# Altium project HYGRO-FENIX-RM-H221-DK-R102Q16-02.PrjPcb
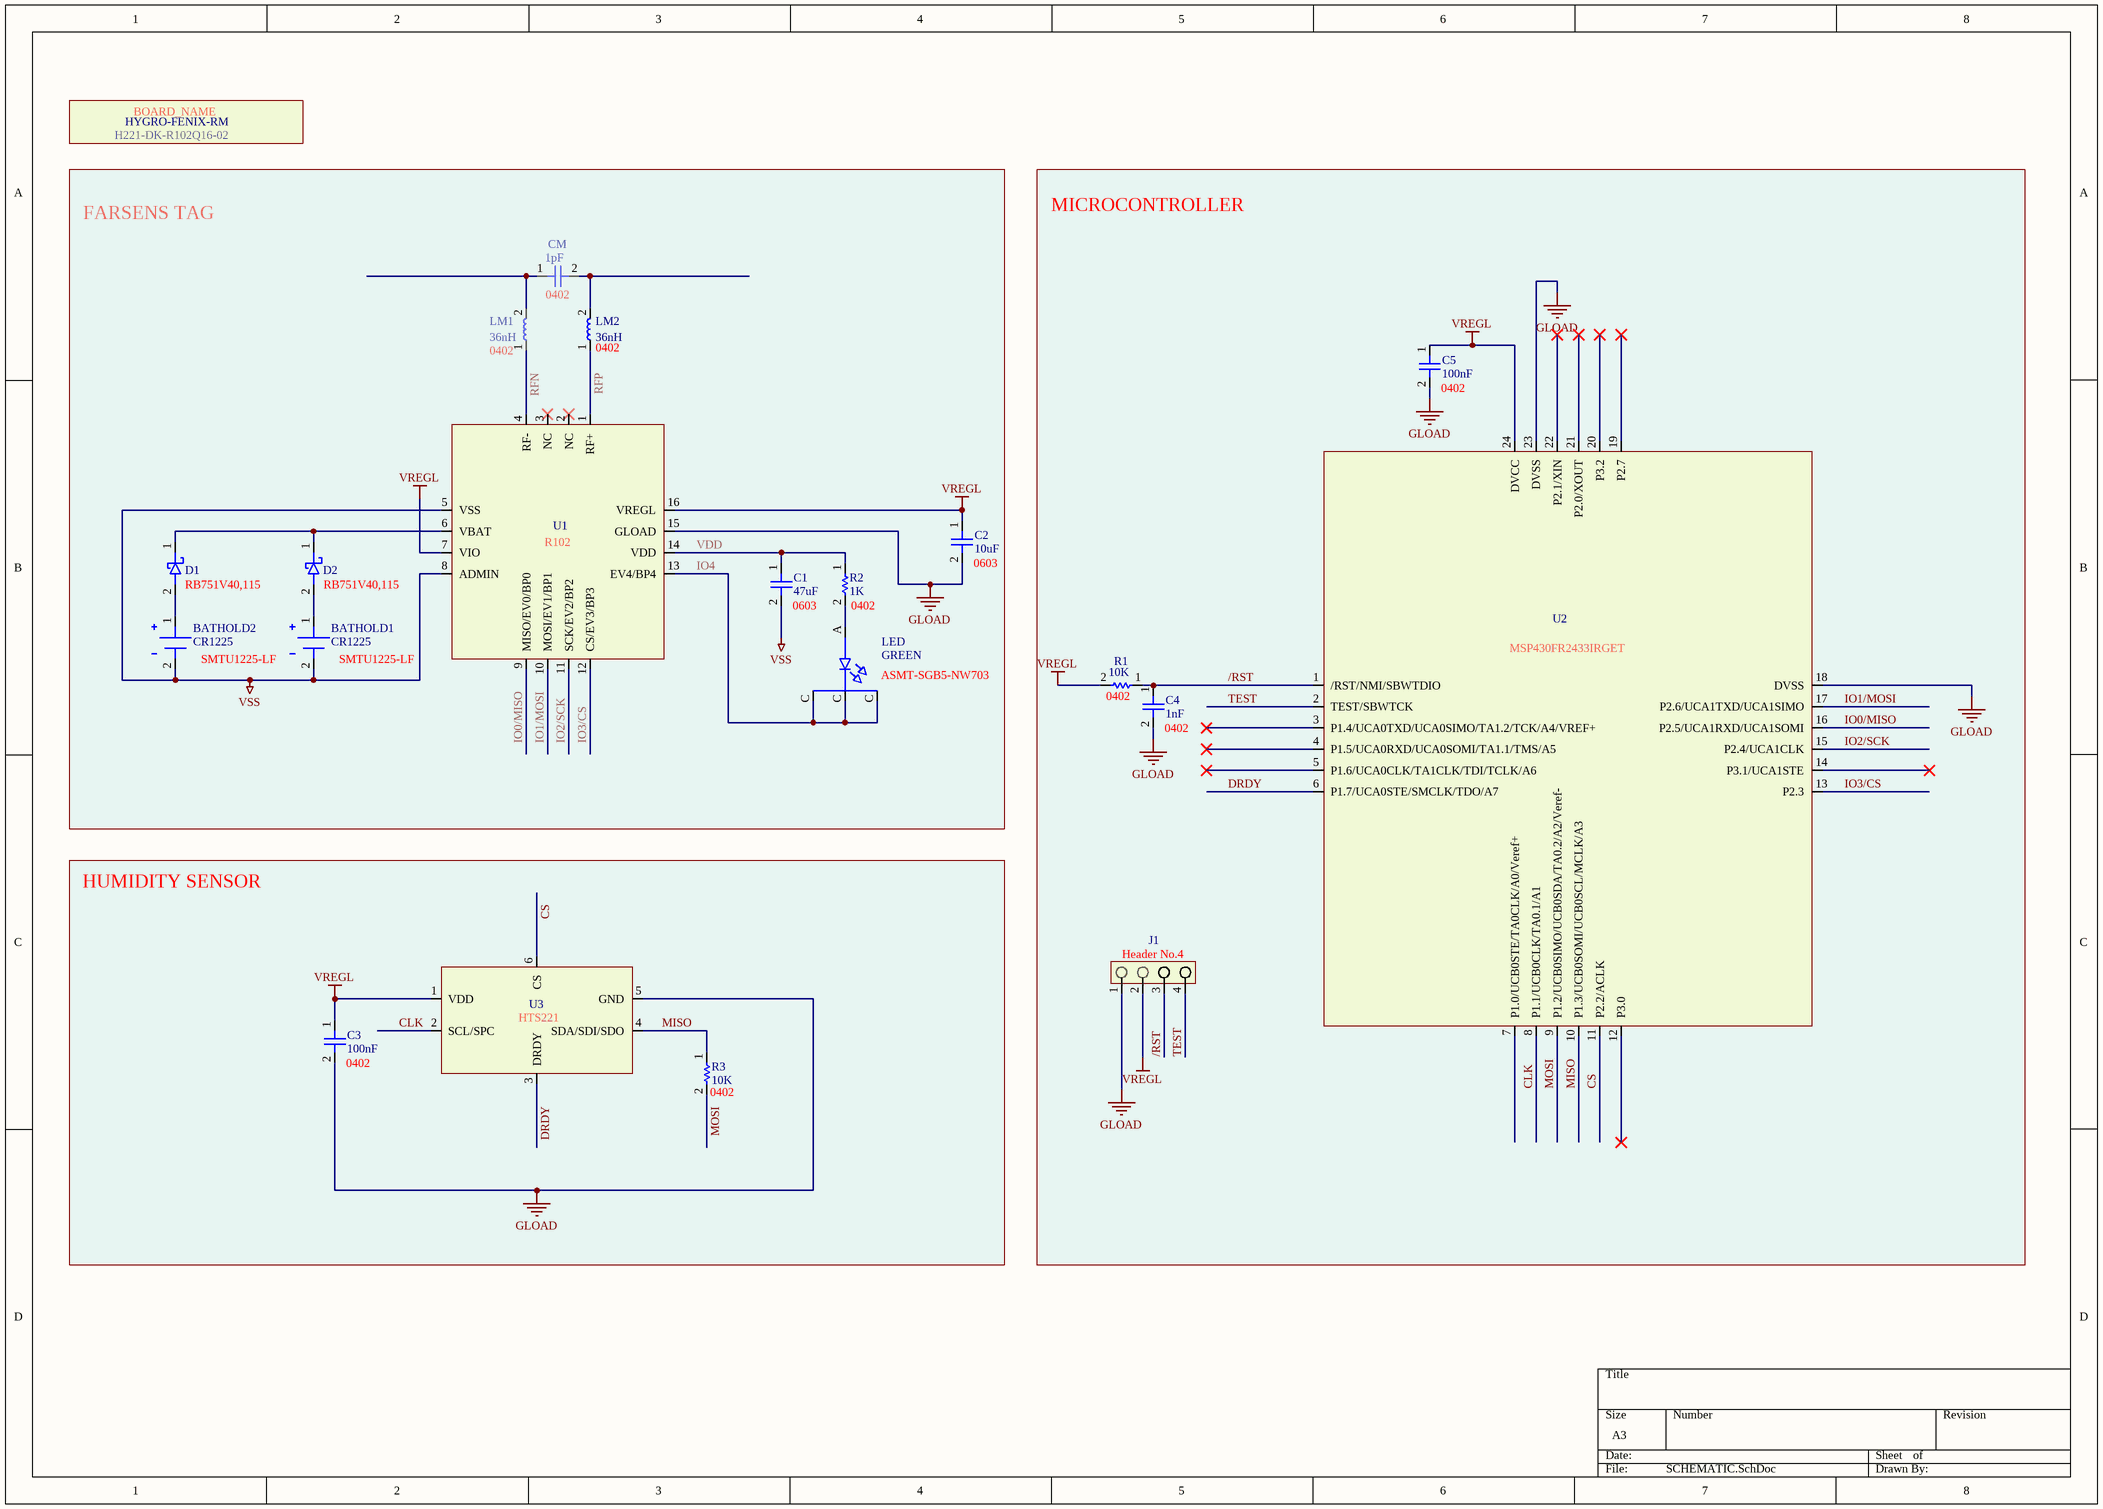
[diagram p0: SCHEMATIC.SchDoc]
1 sheet, 21 parts. Net scope: global (net labels, ports and power ports of the same name join across sheets).
Board file: LAYOUT.PcbDoc

## Sheet SCHEMATIC.SchDoc
size A3

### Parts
BATHOLD1  03 Value: CR1225  [SMTU1225-LF]  (hidden comment: SMTU1225-LF)
BATHOLD2  03 Value: CR1225  [SMTU1225-LF]  (hidden comment: SMTU1225-LF)
C1  03 Value: 47uF  05 Footprint: 0603  [LCR 0603 (1608)]  (hidden comment: Capacitor)
C2  03 Value: 10uF  05 Footprint: 0603  [LCR 0603 (1608)]  (hidden comment: Capacitor)
C3  03 Value: 100nF  05 Footprint: 0402  [LCR 0402 (1005)]  (hidden comment: Capacitor)
C4  03 Value: 1nF  05 Footprint: 0402  [LCR 0402 (1005)]  (hidden comment: Capacitor)
C5  03 Value: 100nF  05 Footprint: 0402  [LCR 0402 (1005)]  (hidden comment: Capacitor)
CM  03 Value: 1pF  05 Footprint: 0402  [LCR 0402 (1005)]  (hidden comment: Capacitor)
D1  RB751V40,115  [RB751V40,115]
D2  RB751V40,115  [RB751V40,115]
HYGRO-FENIX-RM  02 Description: H221-DK-R102Q16-02  [BOARD_NAME]  (hidden comment: BOARD_NAME)
J1  Header No.4  [Header No.4]
LED  03 Value: GREEN  [ASMT-SGB5-NW703]  (hidden comment: ASMT-SGB5-NW703)
LM1  03 Value: 36nH  05 Footprint: 0402  [LCR 0402 (1005)]  (hidden comment: Inductor)
LM2  03 Value: 36nH  05 Footprint: 0402  [LCR 0402 (1005)]  (hidden comment: Inductor)
R1  03 Value: 10K  05 Footprint: 0402  [LCR 0402 (1005)]  (hidden comment: Resistor)
R2  03 Value: 1K  05 Footprint: 0402  [LCR 0402 (1005)]  (hidden comment: Resistor)
R3  03 Value: 10K  05 Footprint: 0402  [LCR 0402 (1005)]  (hidden comment: Resistor)
U1  R102  [R102]
U2  MSP430FR2433IRGET  [MSP430FR2433IRGET]
U3  HTS221  [HTS221]

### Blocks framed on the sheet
FARSENS TAG: BATHOLD1 BATHOLD2 C1 C2 CM D1 D2 LED LM1 LM2 R2 U1
MICROCONTROLLER: C4 C5 J1 R1 U2

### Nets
GLOAD: C2.2 C3.2 C4.2 C5.2 J1.1 U1.15(GLOAD) U2.18(DVSS) U2.23(DVSS) U3.5(GND)
VREGL: C2.1 C3.1 C5.1 J1.2 R1.2 U1.7(VIO) U1.16(VREGL) U2.24(DVCC) U3.1(VDD)
VSS: BATHOLD1.2 BATHOLD2.2 C1.2 U1.5(VSS) U1.8(ADMIN)
/RST: C4.1 J1.3 R1.1 U2.1(/RST/NMI/SBWTDIO)
CLK: U2.8(P1.1/UCB0CLK/TA0.1/A1) U3.2(SCL/SPC)
CS: U2.11(P2.2/ACLK) U3.6(CS)
DRDY: U2.6(P1.7/UCA0STE/SMCLK/TDO/A7) U3.3(DRDY)
IO0/MISO: U1.9(MISO/EV0/BP0) U2.16(P2.5/UCA1RXD/UCA1SOMI)
IO1/MOSI: U1.10(MOSI/EV1/BP1) U2.17(P2.6/UCA1TXD/UCA1SIMO)
IO2/SCK: U1.11(SCK/EV2/BP2) U2.15(P2.4/UCA1CLK)
IO3/CS: U1.12(CS/EV3/BP3) U2.13(P2.3)
IO4: LED.C U1.13(EV4/BP4)
MISO: R3.1 U2.10(P1.3/UCB0SOMI/UCB0SCL/MCLK/A3) U3.4(SDA/SDI/SDO)
MOSI: R3.2 U2.9(P1.2/UCB0SIMO/UCB0SDA/TA0.2/A2/Veref-)
RFN: LM1.1 U1.4(RF-)
RFP: LM2.1 U1.1(RF+)
TEST: J1.4 U2.2(TEST/SBWTCK)
VDD: C1.1 R2.1 U1.14(VDD)
NetBATHOLD1_1: BATHOLD1.1 D2.2
NetBATHOLD2_1: BATHOLD2.1 D1.2
NetCM_1: CM.1 LM1.2
NetCM_2: CM.2 LM2.2
NetD1_1: D1.1 D2.1 U1.6(VBAT)
NetLED_A: LED.A R2.2

Not connected (* = marked no-connect by the designer): U1 2(NC)* 3(NC)*; U2 3(P1.4/UCA0TXD/UCA0SIMO/TA1.2/TCK/A4/VREF+)* 4(P1.5/UCA0RXD/UCA0SOMI/TA1.1/TMS/A5)* 5(P1.6/UCA0CLK/TA1CLK/TDI/TCLK/A6)* 7(P1.0/UCB0STE/TA0CLK/A0/Veref+) 12(P3.0)* 14(P3.1/UCA1STE)* 19(P2.7)* 20(P3.2)* 21(P2.0/XOUT)* 22(P2.1/XIN)*

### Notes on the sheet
- HUMIDITY SENSOR

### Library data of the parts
BATHOLD1 BATHOLD2 = SMTU1225-LF: Battery holder; 06 Manufacturer: RENATA
C1 = Capacitor: 06 Manufacturer: MURATA; 07 Manufacturer Reference: ZRB18AR60J476ME01L; 02 Description: Ceramic Capacitor
C2 = Capacitor: 06 Manufacturer: TDK; 07 Manufacturer Reference: C1608X5R0J106M080AB; 02 Description: Ceramic Capacitor
C3 C5 = Capacitor: 06 Manufacturer: MURATA; 07 Manufacturer Reference: GRM155R71C104KA88D; 02 Description: Ceramic Capacitor
C4 = Capacitor: 06 Manufacturer: MURATA; 07 Manufacturer Reference: GRM155R71H102KA01D; 02 Description: Ceramic Capacitor
CM = Capacitor: 06 Manufacturer: Johanson Dielectrics; 07 Manufacturer Reference: 500R07S1R0BV4T; 02 Description: Ceramic Capacitor
D1 D2 = RB751V40,115: Schottky Diode; 06 Manufacturer: NXP
HYGRO-FENIX-RM = BOARD_NAME: LOGO FARSENS
J1 = Header No.4: 1-Row, 4-Pin, Pitch 2.54mm; 06 Manufacturer: Harwin; 07 Manufacturer Reference: M20-9770442; 02 Description: Male, Thru Hole; 04 Block: R&D
LED = ASMT-SGB5-NW703: RGB triple LED; 06 Manufacturer: AVAGO; 02 Description: GREEN LED
LM1 LM2 = Inductor: 06 Manufacturer: MURATA; 07 Manufacturer Reference: LQW15AN36NG00D
R1 R3 = Resistor: 06 Manufacturer: PANASONIC; 07 Manufacturer Reference: ERJ-2RKF1002X
R2 = Resistor: 06 Manufacturer: SUSUMU; 07 Manufacturer Reference: RR0510P-102-D
U1 = R102: RFID TAG; 06 Manufacturer: FARSENS; 07 Manufacturer Reference: R102Q16; 01 Type: IC; 02 Description: RFID TAG IC; 11 RS Reference: NA
U2 = MSP430FR2433IRGET: Mixed-Signal Microcontroller; 06 Manufacturer: TEXAS INSTRUMENTS; 01 Type: IC
U3 = HTS221: HUMIDITY AND TEMPERATURE SENSOR; 06 Manufacturer: ST Microelectronics; 01 Type: IC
